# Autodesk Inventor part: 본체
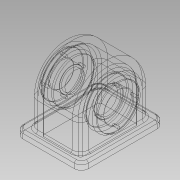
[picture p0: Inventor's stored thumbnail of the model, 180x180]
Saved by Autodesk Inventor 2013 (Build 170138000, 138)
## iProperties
Created: 2018-07
Part Number: 본체
Material: 11111111
Document SubType Name: Modeling
Designer: 05-01
Density: 7 g/cm^3
Mass: 2360.76 g
Surface Area: 768.298 cm^2
Volume: 337.252 cm^3
Author: 05-01
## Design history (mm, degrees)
sketch "스케치1"
  geometry: L1 (-47.5, 60)-(47.5, 60); L2 (47.5, 60)-(47.5, -60); L3 (47.5, -60)-(-47.5, -60); L4 (-47.5, -60)-(-47.5, 60); 3 further points
  constraints: 8 end point, 2 midpoint, 2 parallel, 1 horizontal, 1 horizontal alignment, 1 perpendicular, 1 vertical alignment
  dimensions: "d0" = 95 distance of L1.start L1.end; "d2" = 120 distance of L1.end L2.end
extrude "돌출1" new body sketch "스케치1" distance "d3" = 10; taper "d4" = 0 deg
sketch "스케치2"
  geometry: L1 (60, 0)-(-60, 0) reference; L2 (-51, 50)-(51, 50); L3 (51, 50)-(51, 0); L4 (51, 0)-(-51, 0); L5 (-51, 0)-(-51, 50); A1 r 51 centre (0, 50) between (51, 50) and (-51, 50); 1 further point
  constraints: 8 end point, 2 parallel, 2 point on circle, 1 centre point, 1 horizontal, 1 perpendicular, 1 point on line
  dimensions: "d5" = 102 diameter of A1; "d6" = 50 distance from line of L1 A1.centre
extrude "돌출2" join sketch "스케치2" stored distance "d7" = 74; taper "d8" = 0 deg
sketch "스케치3"
  geometry: L1 (-60, 0)-(60, 0) reference; L2 (42, 0)-(-42, 0); L3 (-42, 50)-(-42, 0); L4 (42, 50)-(42, 0); L5 (51, 50)-(51, 10) reference; A1 r 51 centre (0, 50) between (51, 50) and (-51, 50) reference; A2 r 42 centre (0, 50) between (42, 50) and (-42, 50); 1 further point
  constraints: 6 end point, 2 point on circle, 2 point on line, 1 centre point, 1 collinear, 1 perpendicular, 1 tangent, 1 vertical
  dimensions: "d9" = 9 radial gap between concentric circles of A1 A2; "d10" = 9 distance between parallel lines of L5 L4
extrude "돌출3" cut sketch "스케치3" stored distance "d11" = 56; taper "d12" = 0 deg
sketch "스케치4"
  geometry: C1 r 31 at (-50, 0); A1 r 42 centre (-50, 0) between (-50, 42) and (-50, -42) reference; 1 further point
  constraints: 1 centre point, 1 coincident
  dimensions: "d13" = 62 diameter of C1
extrude "돌출4" join sketch "스케치4" distance "d14" = 6; taper "d15" = 0 deg
sketch "스케치5"
  geometry: C1 r 31 at (50, 0); A1 r 51 centre (50, 0) between (50, -51) and (50, 51) reference; 1 further point
  constraints: 1 centre point, 1 coincident
  dimensions: "d16" = 62 diameter of C1
extrude "돌출5" join sketch "스케치5" distance "d17" = 5; taper "d18" = 0 deg
sketch "스케치6"
  geometry: C1 r 31 at (0, 0) reference; C2 r 17.5 at (0, 0); 1 further point
  constraints: 1 centre point, 1 coincident
  dimensions: "d19" = 35 diameter of C2
extrude "돌출6" cut sketch "스케치6" distance "d20" = 15; taper "d21" = 0 deg
hole "구멍1" diameter "d24" = 29; stored, may be unused: countersink angle "d28" = 90 deg, drill point angle "d30" = 0 deg; dims "d22" = 10, "d23" = 10, "d25" = 6, "d26" = 4, "d27" = 2, "d29" = 5
hole "구멍3" diameter "d45" = 42; stored, may be unused: countersink angle "d49" = 90 deg, drill point angle "d51" = 0 deg; dims "d43" = 10, "d44" = 10, "d46" = 6, "d47" = 4, "d48" = 2, "d50" = 15
hole "구멍4" diameter "d54" = 36; stored, may be unused: countersink angle "d58" = 90 deg, drill point angle "d60" = 0 deg; dims "d52" = 10, "d53" = 10, "d55" = 6, "d56" = 4, "d57" = 2, "d59" = 5
fillet "모깎기1" dims "d61" = 12
fillet "모깎기2" dims "d62" = 3
fillet "모깎기3" dims "d63" = 10
fillet "모깎기4" dims "d64" = 3
sketch "스케치9"
  geometry: C1 r 17.5 at (0, 0) reference; 2 further points
  dimensions: "d65" = 26 distance of point (26, 0) C1.centre
hole "구멍5" sketch "스케치9" at (26, 0) diameter "d66" = 3.242; stored, may be unused: countersink angle "d70" = 90 deg, drill point angle "d72" = 118 deg; dims "d67" = 6, "d68" = 4, "d69" = 2, "d71" = 8
chamfer "모따기1" distance "d76" = 1; stored, may be unused: second distance "d77" = 2, angle "d78" = 45 deg
fillet "모깎기5" dims "d79" = 0.3, "d80" = 0.6
node "솔리드1"
mirror "대칭3"
pattern_circular "원형 패턴1" dims angle "d74" = 360 deg
mirror "대칭4"
